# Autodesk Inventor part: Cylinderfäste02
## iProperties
Shininess: 64.0
Length Units: 11269
Angle Units: 11279
Time Units: 11290
Mass Units: 11283
Length Display Precision: 3
Angle Display Precision: 2
Created: 2001-12
Part Number: Cylinderfäste02
Material: Steel, Mild
Document SubType Name: Modeling
Designer: Tobben
Density: 1 g/cm^3
Density: 0.0
Volumn: 0.0
Area: 0.0
PropertySet Name: Model Information
Control State: 0
Master: False
Checked Out: False
Author: Tobben
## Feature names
1. Extrusion1
2. Hole1
3. Extrusion2
4. Extrusion3
5. Chamfer1
6. Fillet1
7. Extrusion4
8. Extrusion5
9. Fillet2
